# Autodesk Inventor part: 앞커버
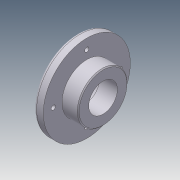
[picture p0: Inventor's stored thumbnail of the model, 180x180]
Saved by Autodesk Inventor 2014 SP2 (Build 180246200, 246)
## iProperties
Company: 한국ATC센터
Created: 2014-11
Part Number: 앞커버
Document SubType Name: Modeling
Designer: KYOUNG IL JANG
Density: 2.71 g/cm^3
Material: 알루미늄-6061
Mass: 204.895 g
Surface Area: 201.401 cm^2
Volume: 75.6071 cm^3
Appearance: 알루미늄 - 평지
Author: KYOUNG IL JANG
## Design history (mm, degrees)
sketch "스케치1"
  geometry: L1 (-13.5, 0)-(13.5, 0); L2 (-13.5, 0)-(-13.5, 45.5); L3 (-13.5, 45.5)-(-3.5, 45.5); L4 (-3.5, 45.5)-(-3.5, 26); L5 (-3.5, 26)-(13.5, 26); L6 (13.5, 26)-(13.5, 0); 2 further points
  constraints: 12 end point, 3 parallel, 2 perpendicular, 1 coincident, 1 horizontal, 1 midpoint
  dimensions: "d0" = 27 distance of L1.start L1.end; "d1" = 91 diameter of L3 L1; "d2" = 52 diameter of L5 L1; "d3" = 10 distance of L2.end L3.end
revolve "회전1" sketch "스케치1" stored, may be unused: angle "d4" = 90 deg
hole "구멍1" diameter "d7" = 30; stored, may be unused: countersink angle "d11" = 90 deg, drill point angle "d13" = 118 deg; dims "d5" = 10, "d6" = 10, "d8" = 6, "d9" = 40, "d10" = 8.3, "d12" = 8
sketch "스케치2"
  geometry: 2 further points
  constraints: 1 vertical alignment
  dimensions: "d14" = 35 distance of point (0, 0) point (0, 35)
hole "구멍2" sketch "스케치2" at (0, 35) diameter "d15" = 4.5; stored, may be unused: countersink angle "d19" = 90 deg, drill point angle "d21" = 118 deg; dims "d16" = 6, "d17" = 8, "d18" = 4.4, "d20" = 8
chamfer "모따기1" distance "d25" = 0.8; stored, may be unused: second distance "d26" = 2, angle "d27" = 30 deg
fillet "모깎기1" dims "d28" = 0.3, "d29" = 3
chamfer "모따기2" distance "d30" = 1; stored, may be unused: second distance "d31" = 2, angle "d32" = 30 deg
node "솔리드1"
pattern_circular "원형 패턴1" dims angle "d23" = 360 deg
